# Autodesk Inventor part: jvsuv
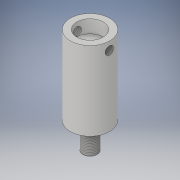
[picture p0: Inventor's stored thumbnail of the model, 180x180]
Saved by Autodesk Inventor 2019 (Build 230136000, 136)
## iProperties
Created: 2019-11
Part Number: jvsuv
Material: Generic
Document SubType Name: Sheet Metal
Designer: PRADYUMNA
Density: 1 g/cm^3
Sheet Metal Rule: Default_mm
Appearance: Default
Author: PRADYUMNA
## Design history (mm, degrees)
sketch "Sketch1"
  geometry: C1 r 7.5 at (0, 0); 1 further point
  constraints: 1 centre point, 1 coincident
  dimensions: "d0" = 15 diameter of C1
extrude "Extrusion1" new body sketch "Sketch1" distance "d1" = 30; taper "d2" = 0 deg
sketch "Sketch2"
  geometry: C1 r 5.054 at (0, 0); 1 further point
  constraints: 1 centre point, 1 coincident
extrude "Extrusion2" cut sketch "Sketch2" distance "d3" = 5; taper "d4" = 0 deg
sketch "Sketch3"
  geometry: C1 r 1.589 at (26.824, 0); 1 further point
  constraints: 1 centre point
extrude "Extrusion3" cut sketch "Sketch3" stored distance "d5" = 100; taper "d6" = 0 deg
thread "Thread1" dims "d7" = 10, "d8" = 0
thread "Thread2" dims "d9" = 10, "d10" = 0
sketch "Sketch4"
  geometry: C1 r 2.747 at (0, 0); 1 further point
  constraints: 1 centre point, 1 coincident
extrude "Extrusion4" join sketch "Sketch4" distance "d11" = 10; taper "d12" = 0 deg
thread "Thread3" dims "d13" = 10, "d14" = 0
body "Solid1"
other parameters: "Thickness" = 0.5, "BendRadius" = 0.5 (= Thickness), "BendReliefWidth" = 0.5 (= Thickness), "BendReliefDepth" = 0.25 (= 0.5 x Thickness), "CornerReliefSize" = 2 (= 4 x Thickness), "SeamGap" = 0.01, "MinimumRemnant" = 1 (= 2 x Thickness), "TransitionRadius" = 0.5 (= BendRadius), "JacobiRadiusSize" = 0.5 (= BendRadius), "GapSize" = 0.5 (= Thickness)
